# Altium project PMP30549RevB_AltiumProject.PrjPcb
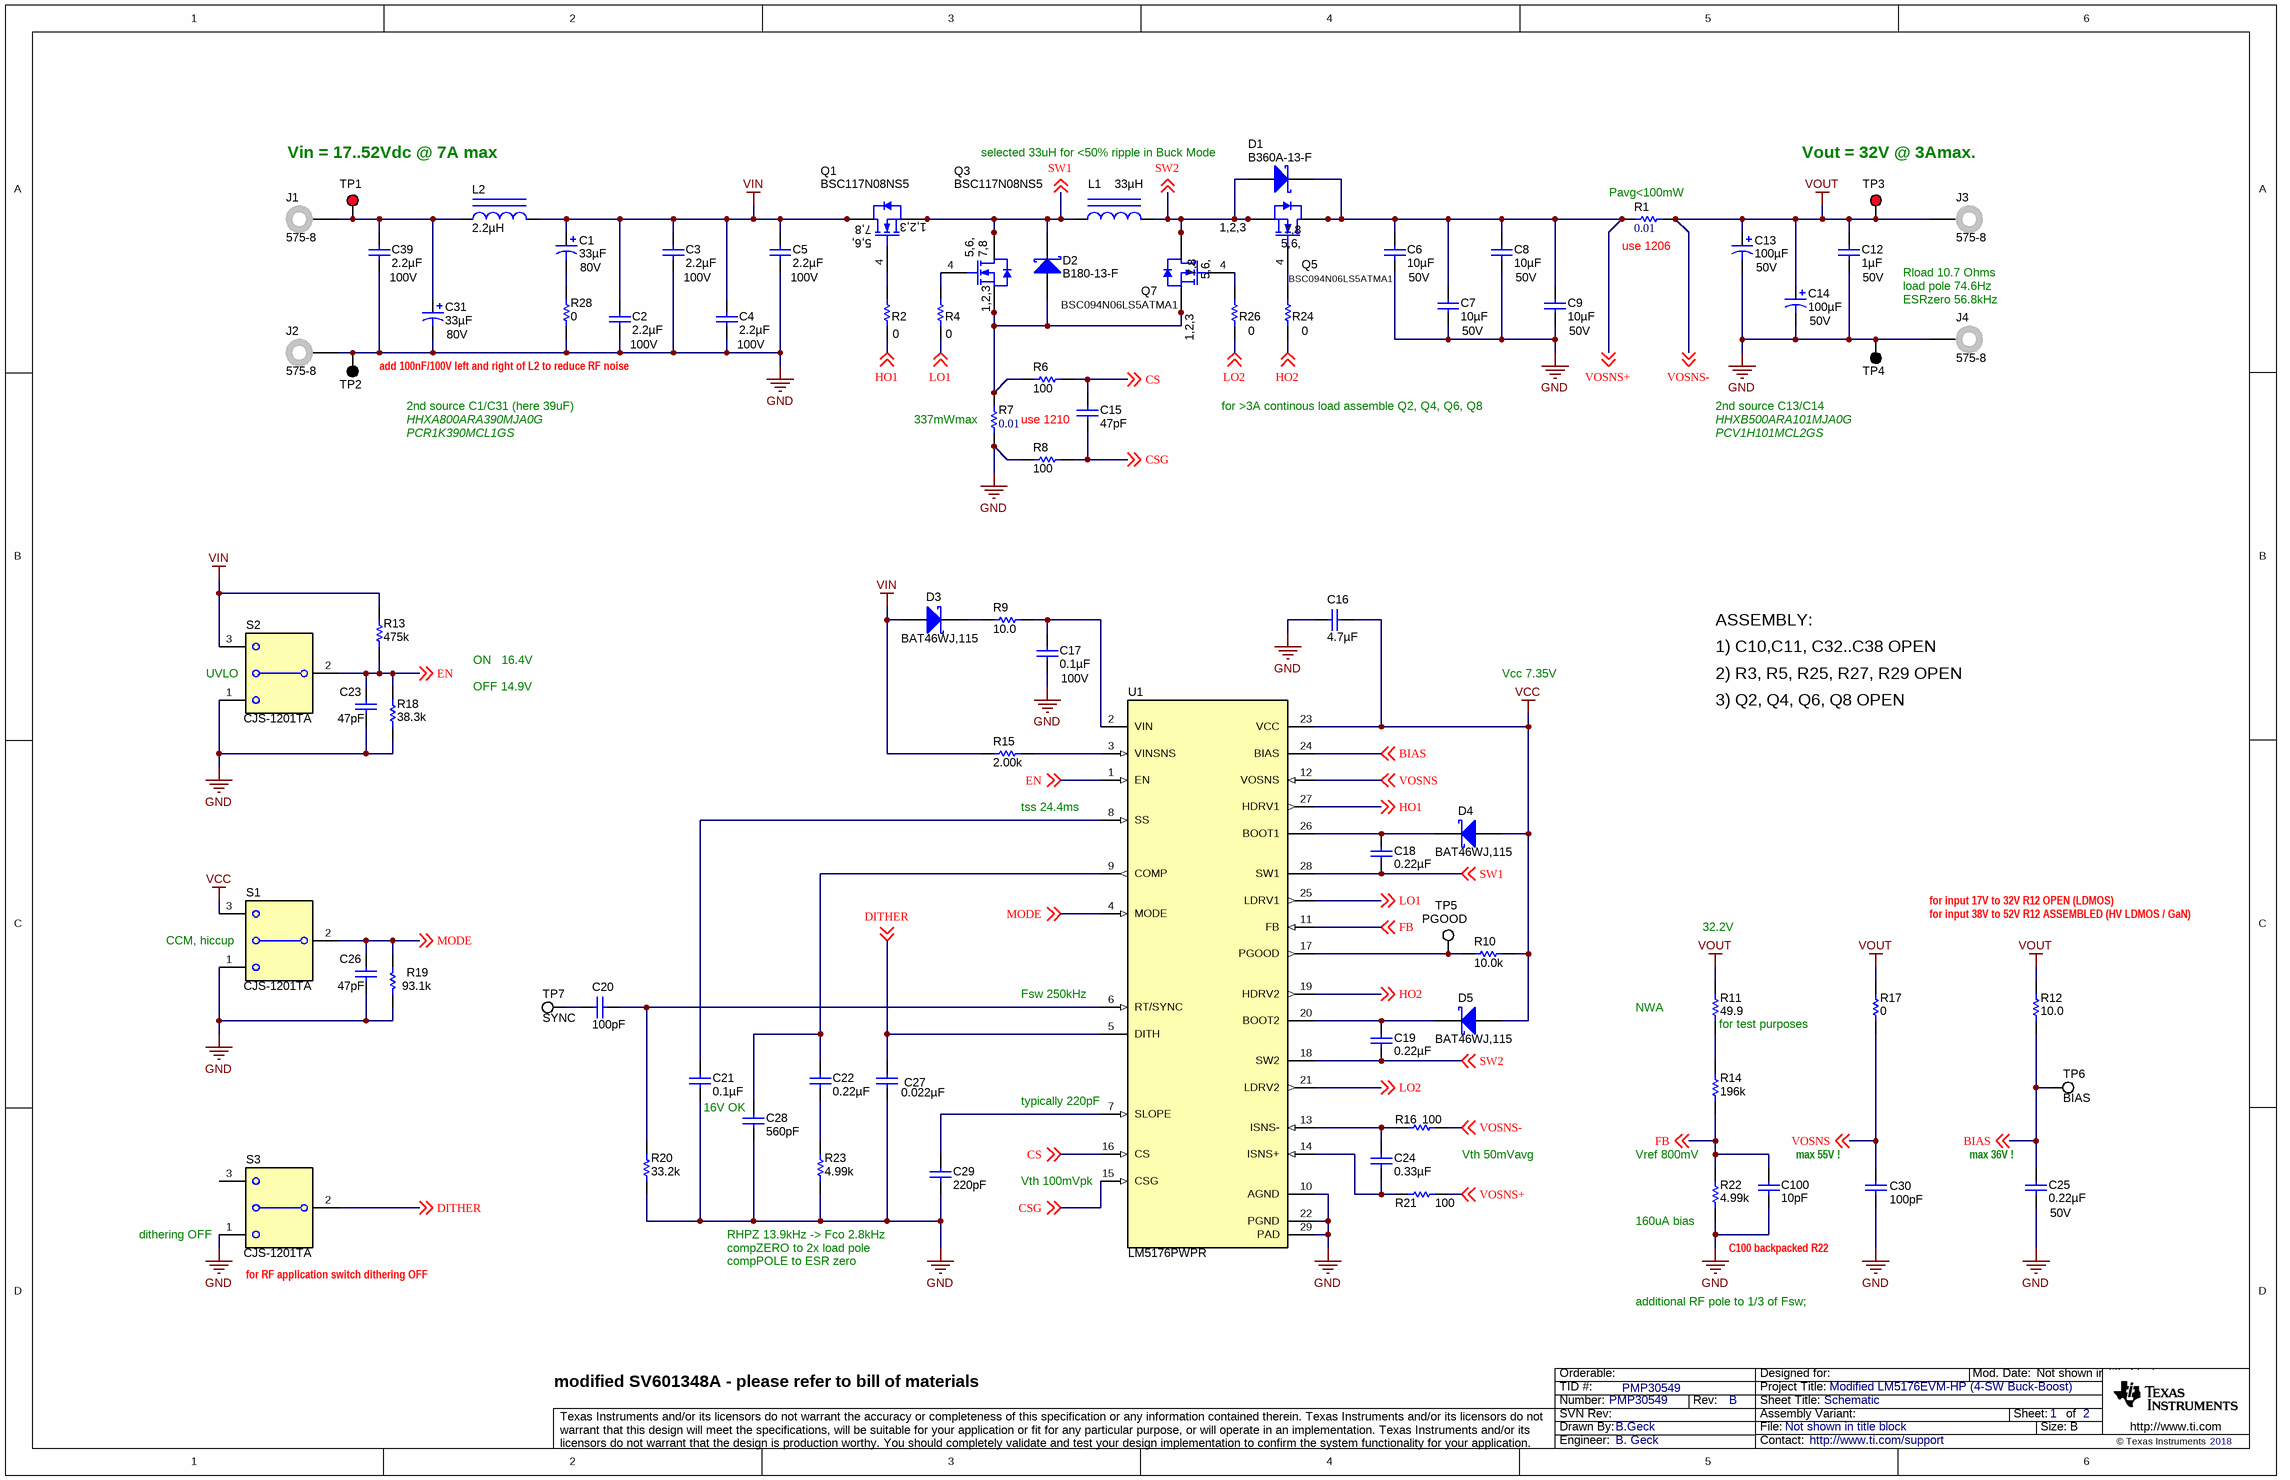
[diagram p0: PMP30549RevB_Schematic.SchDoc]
CopyrightYear: 2018; PCB_Rev: A; PRJ_Engineer: B. Geck; PRJ_Number: PMP30549; PRJ_Title: Modified LM5176EVM-HP (4-SW Buck-Boost); SCH_Rev: B; TechSupport: http://www.ti.com/support; TID: PMP30549
2 sheets, 98 parts. Net scope: global (net labels, ports and power ports of the same name join across sheets).
Sheets:
  PMP30549RevB_Schematic.SchDoc
  PMP30549_EVM_Hardware.SchDoc

## Sheet PMP30549RevB_Schematic.SchDoc: Schematic
size 431 x 279 mm; Date: Not shown in title block; ApprovedBy: Not shown in title block; CheckedBy: Not shown in title block; Author: Not shown in title block; CompanyName: Not shown in title block; DrawnBy: B.Geck; Engineer: Neil Gutierrez; Organization: Not shown in title block; Address1: Not shown in title block; Address2: Not shown in title block; Address3: Not shown in title block; Address4: Not shown in title block; DocumentNumber: 1; Revision: Use project parameter SCH_Rev; SheetNumber: 1; SheetTotal: 2; PageSetup: Record=PageOptions¦CenterHorizontal=True¦CenterVertical=True¦PrintScale=0.62¦XCorrection=1.00¦YCorrection=1.00¦PrintKind=0¦BorderSize=5000000¦LeftOffset=0¦BottomOffset=0¦Orientation=2¦PaperLength=1000¦PaperWidth=1000¦Scale=100¦PaperSource=15¦PrintQuality=600¦MediaType=1¦DitherType=10¦PaperKind=Letter¦PrintScaleMode=1

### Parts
C1  ValueDisplayed: 33µF  Value2: 80V  [SM_RADIAL_10BMM]  (hidden comment: EEHZA1K330P)
C2  ValueDisplayed: 2.2µF  Value2: 100V  [1210_270]  (hidden comment: GRM32ER72A225KA35L)
C3  ValueDisplayed: 2.2µF  Value2: 100V  [1210_270]  (hidden comment: GRM32ER72A225KA35L)
C4  ValueDisplayed: 2.2µF  Value2: 100V  [1210_270]  (hidden comment: GRM32ER72A225KA35L)
C5  ValueDisplayed: 2.2µF  Value2: 100V  [1210_270]  (hidden comment: GRM32ER72A225KA35L)
C6  ValueDisplayed: 10µF  Value2: 50V  [1210_270]  (hidden comment: GRM32ER71H106KA12L)
C7  ValueDisplayed: 10µF  Value2: 50V  [1210_270]  (hidden comment: GRM32ER71H106KA12L)
C8  ValueDisplayed: 10µF  Value2: 50V  [1210_270]  (hidden comment: GRM32ER71H106KA12L)
C9  ValueDisplayed: 10µF  Value2: 50V  [1210_270]  (hidden comment: GRM32ER71H106KA12L)
C12  ValueDisplayed: 1µF  Value2: 50V  [0805_HV]  (hidden comment: GRM21BR71H105KA12L)
C13  ValueDisplayed: 100µF  Value2: 50V  [SM_RADIAL_10BMM]  (hidden comment: EEHZA1H101P)
C14  ValueDisplayed: 100µF  Value2: 50V  [SM_RADIAL_10BMM]  (hidden comment: EEHZA1H101P)
C15  ValueDisplayed: 47pF  [0603L]  (hidden comment: GRM1885C1H470JA01D)
C16  ValueDisplayed: 4.7µF  [0805_HV]  (hidden comment: GRM21BR71C475KA73L)
C17  ValueDisplayed: 0.1µF  Value2: 100V  [0603L]  (hidden comment: GRM188R72A104KA35D)
C18  ValueDisplayed: 0.22µF  [0603L]  (hidden comment: GRM188R71E224KA88D)
C19  ValueDisplayed: 0.22µF  [0603L]  (hidden comment: GRM188R71E224KA88D)
C20  ValueDisplayed: 100pF  [0603L]  (hidden comment: GRM1885C2A101JA01D)
C21  ValueDisplayed: 0.1µF  [0603L]  (hidden comment: GRM188R72A104KA35D)
C22  ValueDisplayed: 0.22µF  [0603]  (hidden comment: GRM188R71E224KA88D)
C23  47pF  [0603L]
C24  ValueDisplayed: 0.33µF  [0603L]  (hidden comment: GRM188R71C334KA01D)
C25  ValueDisplayed: 0.22µF  Value2: 50V  [0603]  (hidden comment: GRM188R71H224KAC4D)
C26  47pF  [0603L]
C27  ValueDisplayed: 0.022µF  [0603L]  (hidden comment: C0603C223K5RACTU)
C28  ValueDisplayed: 560pF  [0603]  (hidden comment: GRM188R71H561KA01D)
C29  ValueDisplayed: 220pF  [0603]  (hidden comment: GRM188R71H221KA01D)
C30  ValueDisplayed: 100pF  [0603L]  (hidden comment: GRM1885C2A101JA01D)
C31  ValueDisplayed: 33µF  Value2: 80V  [SM_RADIAL_10BMM]  (hidden comment: EEHZA1K330P)
C39  ValueDisplayed: 2.2µF  Value2: 100V  [1210_270]  (hidden comment: GRM32ER72A225KA35L)
C100  ValueDisplayed: 10pF  [0603]  (hidden comment: GRM1885C1H100JA01D)
D1  B360A-13-F  [SMA]
D2  B180-13-F  [SMA]
D3  BAT46WJ,115  [SOD-323F]
D4  BAT46WJ,115  [SOD-323F]
D5  BAT46WJ,115  [SOD-323F]
J1  575-8  [Keystone575-8]
J2  575-8  [Keystone575-8]
J3  575-8  [Keystone575-8]
J4  575-8  [Keystone575-8]
L1  ValueDisplayed: 33µH  [XAL1510]  (hidden comment: XAL1510-333MEB)
L2  ValueDisplayed: 2.2µH  [XAL5030]  (hidden comment: XAL5030-222MEB)
Q1  BSC117N08NS5  [PG-TDSON-8]
Q3  BSC117N08NS5  [PG-TDSON-8]
Q5  BSC094N06LS5ATMA1  [PG-TDSON-8]
Q7  BSC094N06LS5ATMA1  [PG-TDSON-8]
R1  ValueDisplayed: 0.01  [2512_WIDE]  (hidden comment: FCSL64R010FER)
R2  value 0  [0603L]  (hidden comment: RC0603JR-070RL)
R4  value 0  [0603L]  (hidden comment: RC0603JR-070RL)
R6  value 100  [0603_HV]  (hidden comment: RC0603FR-07100RL)
R7  ValueDisplayed: 0.01  [2512_WIDE]  (hidden comment: FCSL64R010FER)
R8  value 100  [0603_HV]  (hidden comment: RC0603FR-07100RL)
R9  value 10.0  [0603L]  (hidden comment: RC0603FR-0710RL)
R10  value 10.0k  [0603L]  (hidden comment: RC0603FR-0710KL)
R11  ValueDisplayed: 49.9  [0603]  (hidden comment: CRCW060349R9FKEA)
R12  value 10.0  [0603L]  (hidden comment: RC0603FR-0710RL)
R13  ValueDisplayed: 475k  [0603]  (hidden comment: CRCW0603475KFKEA)
R14  ValueDisplayed: 196k  [0603]  (hidden comment: CRCW0603196KFKEA)
R15  ValueDisplayed: 2.00k  [0603]  (hidden comment: CRCW06032K00FKEA)
R16  100  [0603L]
R17  value 0  [0603L]  (hidden comment: RC0603JR-070RL)
R18  ValueDisplayed: 38.3k  [0603]  (hidden comment: CRCW060338K3FKEA)
R19  ValueDisplayed: 93.1k  [0603L]  (hidden comment: RC0603FR-0793K1L)
R20  ValueDisplayed: 33.2k  [0603L]  (hidden comment: CRCW060333K2FKEA)
R21  100  [0603L]
R22  ValueDisplayed: 4.99k  [0603]  (hidden comment: CRCW06034K99FKEA)
R23  ValueDisplayed: 4.99k  [0603]  (hidden comment: CRCW06034K99FKEA)
R24  value 0  [0603L]  (hidden comment: RC0603JR-070RL)
R26  value 0  [0603L]  (hidden comment: RC0603JR-070RL)
R28  ValueDisplayed: 0  [1206]  (hidden comment: CRCW12060000Z0EA)
S1  CJS-1201TA  [SW_CJS_1201A]
S2  CJS-1201TA  [SW_CJS_1201A]
S3  CJS-1201TA  [SW_CJS_1201A]
TP1  5005  [Keystone5005]  (value not drawn)
TP2  5006  [Keystone5006]  (value not drawn)
TP3  5005  [Keystone5005]  (value not drawn)
TP4  5006  [Keystone5006]  (value not drawn)
TP5  PGOOD  [Keystone5007]
TP6  BIAS  [Keystone5007]
TP7  SYNC  [Keystone5007]
U1  LM5176PWPR  [PWP0028C_N]

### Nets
GND: C2.2 C3.2 C4.2 C5.2 C6.2 C7.2 C8.2 C9.2 C12.2 C13.2(-) C14.2(-) C16.1 C17.2 C21.2 C23.2 C25.2 C26.2 C27.2 C28.2 C29.2 C30.2 C31.2(-) C39.2 C100.2 J2.1 J4.1 R7.1 R8.2 R18.1 R19.1 R20.1 R22.1 R23.1 R28.1 S1.1 S2.1 S3.1 TP2.1 TP4.1 U1.10(AGND) U1.22(PGND) U1.29(PAD)
VCC: C16.2 D4.2(A) D5.2(A) R10.2 S1.3 U1.23(VCC)
VIN: C1.1(+) C2.1 C3.1 C4.1 C5.1 D3.2(A) L2.2 Q1.5(D) Q1.6(D) Q1.7(D) Q1.8(D) Q1.9(D) R13.2 R15.2 S2.3
VOUT: C12.1 C13.1(+) C14.1(+) J3.1 R1.1 R11.2 R12.1 R16.2 R17.1 TP3.1 ; off-sheet VOSNS-  [also labelled VOSNS-]
BIAS: C25.1 R12.2 TP6.1 U1.24(BIAS) ; off-sheet BIAS
CS: C15.1 R6.1 U1.16(CS) ; off-sheet CS
CSG: C15.2 R8.1 U1.15(CSG) ; off-sheet CSG
DITHER: C27.1 S3.2(COM) U1.5(DITH) ; off-sheet DITHER
EN: C23.1 R13.1 R18.2 S2.2(COM) U1.1(EN) ; off-sheet EN
FB: C100.1 R14.1 R22.2 U1.11(FB) ; off-sheet FB
HO1: R2.2 U1.27(HDRV1) ; off-sheet HO1
HO2: R24.2 U1.19(HDRV2) ; off-sheet HO2
LO1: R4.2 U1.25(LDRV1) ; off-sheet LO1
LO2: R26.2 U1.21(LDRV2) ; off-sheet LO2
MODE: C26.1 R19.2 S1.2(COM) U1.4(MODE) ; off-sheet MODE
SW1: C18.1 D2.1(K) L1.1 Q1.1(S) Q1.2(S) Q1.3(S) Q3.5(D) Q3.6(D) Q3.7(D) Q3.8(D) Q3.9(D) U1.28(SW1) ; off-sheet SW1
SW2: C19.2 D1.2(A) L1.2 Q5.1(S) Q5.2(S) Q5.3(S) Q7.5(D) Q7.6(D) Q7.7(D) Q7.8(D) Q7.10(D) U1.18(SW2) ; off-sheet SW2
VOSNS: C30.1 R17.2 U1.12(VOSNS) ; off-sheet VOSNS
VOSNS+: C6.1 C7.1 C8.1 C9.1 D1.1(K) Q5.5(D) Q5.6(D) Q5.7(D) Q5.8(D) Q5.10(D) R1.2 R21.2 ; off-sheet VOSNS+
NetC1_2: C1.2(-) R28.2
NetC17_1: C17.1 R9.1 U1.2(VIN)
NetC18_2: C18.2 D4.1(K) U1.26(BOOT1)
NetC19_1: C19.1 D5.1(K) U1.20(BOOT2)
NetC20_1: C20.1 TP7.1
NetC20_2: C20.2 R20.2 U1.6(RT/SYNC)
NetC21_1: C21.1 U1.8(SS)
NetC22_1: C22.1 C28.1 U1.9(COMP)
NetC22_2: C22.2 R23.2
NetC24_1: C24.1 R16.1 U1.13(ISNS-)
NetC24_2: C24.2 R21.1 U1.14(ISNS+)
NetC29_1: C29.1 U1.7(SLOPE)
NetC31_1: C31.1(+) C39.1 J1.1 L2.1 TP1.1
NetD2_2: D2.2(A) Q3.1(S) Q3.2(S) Q3.3(S) Q7.1(S) Q7.2(S) Q7.3(S) R6.2 R7.2
NetD3_1: D3.1(K) R9.2
NetQ1_4: Q1.4(G) R2.1
NetQ3_4: Q3.4(G) R4.1
NetQ5_4: Q5.4(G) R24.1
NetQ7_4: Q7.4(G) R26.1
NetR10_1: R10.1 TP5.1 U1.17(PGOOD)
NetR11_1: R11.1 R14.2
NetR15_1: R15.1 U1.3(VINSNS)

Not connected (* = marked no-connect by the designer): S3 3

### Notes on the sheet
- Vin = 17..52Vdc @ 7A max
- selected 33uH for <50% ripple in Buck Mode
- Vout = 32V @ 3Amax.
- (near R1) Pavg<100mW
- (near R1) use 1206
- Rload 10.7 Ohms
- load pole 74.6Hz
- ESRzero 56.8kHz
- add 100nF/100V left and right of L2 to reduce RF noise
- HHXA800ARA390MJA0G
- PCR1K390MCL1GS
- 2nd source C1/C31 (here 39uF)
- (near R7) 337mWmax
- use 1210
- for >3A continous load assemble Q2, Q4, Q6, Q8
- 2nd source C13/C14
- HHXB500ARA101MJA0G
- PCV1H101MCL2GS
- ASSEMBLY:
- (near S2) UVLO
- ON   16.4V
- OFF 14.9V
- Vcc 7.35V
- 1) C10,C11, C32..C38 OPEN
- 2) R3, R5, R25, R27, R29 OPEN
- 3) Q2, Q4, Q6, Q8 OPEN
- tss 24.4ms
- for input 17V to 32V R12 OPEN (LDMOS)
- (near S1) CCM, hiccup
- 32.2V
- for input 38V to 52V R12 ASSEMBLED (HV LDMOS / GaN)
- (near U1) Fsw 250kHz
- NWA
- (near R11) for test purposes
- 16V OK
- (near U1) typically 220pF
- Vth 50mVavg
- (near R22) Vref 800mV
- max 55V !
- (near C25) max 36V !
- (near S3) dithering OFF
- RHPZ 13.9kHz -> Fco 2.8kHz
- (near U1) Vth 100mVpk
- (near R22) 160uA bias
- (near S3) for RF application switch dithering OFF
- compZERO to 2x load pole
- compPOLE to ESR zero
- additional RF pole to 1/3 of Fsw;
- C100 backpacked R22
- modified SV601348A - please refer to bill of materials

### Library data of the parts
C1 C31 = EEHZA1J560P: CAP, Polymer Hybrid, 33 µF, 80 V,+/- 20%, 36 ohm, 10x10 SMD; Manufacturer: Panasonic; Polarized: Y; CompType: Capacitor; Value: 33uF; U/M: EA; Cap_F: 0.000033; Tolerance_%: 20; Value1: 36 ohm; VDC_V: 80; ESR_ohm: 36; IRMS_A: 1.7; TaMin_C: -55; TaMax_C: 105; SizeAreaWB_mm2: 159.9; SizeArea_mm2: 113.3; SizeX_mm: 11; SizeY_mm: 10.3; SizeZ_mm: 10.2; AEC Category: Q200
C2-C5 C39 = GRM32ER72A225KA35L: CAP, CERM, 2.2 µF, 100 V,+/- 10%, X7R, 1210; Manufacturer: MuRata; Polarized: N; CompType: Capacitor; Value: 2.2uF; U/M: EA; Cap_F: 0.0000022; Tolerance_%: 10; ESR_ohm: 0.007; Value1: 0.007 ohm; VDC_V: 100; IRMS_A: 4.4; TaMin_C: -55; TaMax_C: 125; Cap_Case: 1210; SizeArea_mm2: 8; SizeAreaWB_mm2: 14.7; SizeX_mm: 3.2; SizeY_mm: 2.5; SizeZ_mm: 2.7; AEC Category: Q200; Green_Lifecycle: Active; Green_REACh: Passed
C6-C9 = GRM32ER71H106KA12L: CAP, CERM, 10 µF, 50 V,+/- 10%, X7R, 1210; Manufacturer: MuRata; Polarized: N; CompType: Capacitor; Value: 10uF; U/M: EA; Cap_F: 0.00001; Tolerance_%: 10; VDC_V: 50; TaMin_C: -55; TaMax_C: 125; Cap_Case: 1210; SizeArea_mm2: 8; SizeAreaWB_mm2: 14.7; SizeX_mm: 3.2; SizeY_mm: 2.5; SizeZ_mm: 2.7; AEC Category: Q200; Green_Lifecycle: Active; Green_REACh: Passed
C12 = GRM21BR71H105KA12L: CAP, CERM, 1 µF, 50 V,+/- 10%, X7R, 0805; Manufacturer: MuRata; Polarized: N; CompType: Capacitor; Value: 1uF; U/M: EA; Cap_F: 0.000001; Tolerance_%: 10; VDC_V: 50; TaMin_C: -55; TaMax_C: 125; Cap_Case: 0805; SizeArea_mm2: 2.5; SizeAreaWB_mm2: 6.75; SizeX_mm: 2; SizeY_mm: 1.25; SizeZ_mm: 1.45; AEC Category: Q200; Green_Lifecycle: Active; Green_REACh: Passed
C13 C14 = EEHZA1H101P: CAP, Polymer Hybrid, 100 µF, 50 V,+/- 20%, 28 ohm, 10x10 SMD; Manufacturer: Panasonic; Polarized: Y; CompType: Capacitor; Value: 100uF; U/M: EA; Cap_F: 0.0001; Tolerance_%: 20; Value1: 28 ohm; VDC_V: 50; ESR_ohm: 28; IRMS_A: 2; TaMin_C: -55; TaMax_C: 105; SizeAreaWB_mm2: 159.9; SizeArea_mm2: 113.3; SizeX_mm: 11; SizeY_mm: 10.3; SizeZ_mm: 10.2; AEC Category: Q200
C15 C23 C26 = GRM1885C1H470JA01D: CAP, CERM, 47pF, 50V, +/-5%, C0G/NP0, 0603; Manufacturer: MuRata; Polarized: N; CompType: Capacitor; U/M: EA; Cap_F: 0.000000000047; Tolerance_%: 5; Value1: Unknown; VDC_V: 50; TaMin_C: -55; TaMax_C: 125; Cap_Case: 0603
C16 = GRM21BR71C475KA73L: CAP, CERM, 4.7 µF, 16 V, +/- 10%, X7R, 0805; Manufacturer: MuRata; Polarized: N; CompType: Capacitor; Value: 4.7uF; U/M: EA; Cap_F: 0.0000047; Tolerance_%: 10; ESR_ohm: 0.006; Value1: 0.006 ohm; VDC_V: 16; Value2: 16V; TaMin_C: -55; TaMax_C: 125; Cap_Case: 0805
C17 C21 = GRM188R72A104KA35D: CAP, CERM, 0.1uF, 100V, +/-10%, X7R, 0603; Manufacturer: MuRata; Polarized: N; CompType: Capacitor; U/M: EA; Cap_F: 0.0000001; Tolerance_%: 10; Value1: Unknown; VDC_V: 100; TaMin_C: -55; TaMax_C: 125; Cap_Case: 0603
C18 C19 = GRM188R71E224KA88D: CAP, CERM, 0.22 µF, 25 V, +/- 10%, X7R, 0603; Manufacturer: MuRata; Polarized: N; CompType: Capacitor; Value: 0.22uF; U/M: EA; Cap_F: 0.00000022; Tolerance_%: 10; Value1: Unknown; VDC_V: 25; Value2: 25V; TaMin_C: -55; TaMax_C: 125; Cap_Case: 0603
C20 C30 = GRM1885C2A101JA01D: CAP, CERM, 100pF, 100V, +/-5%, C0G/NP0, 0603; Manufacturer: MuRata; Polarized: N; CompType: Capacitor; U/M: EA; Cap_F: 0.0000000001; Tolerance_%: 5; Value1: Unknown; VDC_V: 100; TaMin_C: -55; TaMax_C: 125; Cap_Case: 0603
C22 = GRM188R71E224KA88D: CAP, CERM, 0.22 µF, 25 V,+/- 10%, X7R, 0603; Manufacturer: MuRata; Polarized: N; CompType: Capacitor; Value: 0.22uF; U/M: EA; Cap_F: 0.00000022; Tolerance_%: 10; VDC_V: 25; Value2: 25V; TaMin_C: -55; TaMax_C: 125; SizeArea_mm2: 1.28; SizeAreaWB_mm2: 4.68; SizeX_mm: 1.6; SizeY_mm: 0.8; SizeZ_mm: 1; AEC Category: Q200; Green_Lifecycle: Active; Green_REACh: Passed
C24 = GRM188R71C334KA01D: CAP, CERM, 0.33 µF, 16 V, +/- 10%, X7R, 0603; Manufacturer: MuRata; Polarized: N; CompType: Capacitor; Value: 0.33uF; U/M: EA; Cap_F: 0.00000033; Tolerance_%: 10; Value1: Unknown; VDC_V: 16; Value2: 16V; TaMin_C: -55; TaMax_C: 125; Cap_Case: 0603
C25 = GRM188R71H224KAC4D: CAP, CERM, 0.22 µF, 50 V,+/- 10%, X7R, 0603; Manufacturer: MuRata; Polarized: N; CompType: Capacitor; Value: 0.22uF; U/M: EA; Cap_F: 0.00000022; Tolerance_%: 10; VDC_V: 50; TaMin_C: -55; TaMax_C: 125; SizeArea_mm2: 1.28; SizeAreaWB_mm2: 4.68; SizeX_mm: 1.6; SizeY_mm: 0.8; SizeZ_mm: 1; AEC Category: Q200
C27 = C0603C223K5RACTU: CAP, CERM, 0.022uF, 50V, +/-10%, X7R, 0603; Manufacturer: Kemet; Polarized: N; CompType: Capacitor; U/M: EA; Cap_F: 0.000000022; Tolerance_%: 10; Value1: Unknown; VDC_V: 50; TaMin_C: -55; TaMax_C: 125; Cap_Case: 0603
C28 = GRM188R71H561KA01D: CAP, CERM, 560 pF, 50 V,+/- 10%, X7R, 0603; Manufacturer: MuRata; Polarized: N; CompType: Capacitor; Value: 560pF; U/M: EA; Cap_F: 0.00000000056; Tolerance_%: 10; VDC_V: 50; Value2: 50V; TaMin_C: -55; TaMax_C: 125; SizeArea_mm2: 1.28; SizeAreaWB_mm2: 4.68; SizeX_mm: 1.6; SizeY_mm: 0.8; SizeZ_mm: 1; AEC Category: Q200
C29 = GRM188R71H221KA01D: CAP, CERM, 220 pF, 50 V,+/- 10%, X7R, 0603; Manufacturer: MuRata; Polarized: N; CompType: Capacitor; Value: 220pF; U/M: EA; Cap_F: 0.00000000022; Tolerance_%: 10; VDC_V: 50; Value2: 50V; TaMin_C: -55; TaMax_C: 125; SizeArea_mm2: 1.28; SizeAreaWB_mm2: 4.68; SizeX_mm: 1.6; SizeY_mm: 0.8; SizeZ_mm: 1; AEC Category: Q200; Green_Lifecycle: Active; Green_REACh: Passed
C100 = GRM1885C1H100JA01D: CAP, CERM, 10 pF, 50 V,+/- 5%, C0G/NP0, 0603; Manufacturer: MuRata; Polarized: N; CompType: Capacitor; Value: 10pF; U/M: EA; Cap_F: 0.00000000001; Tolerance_%: 5; VDC_V: 50; Value2: 50V; TaMin_C: -55; TaMax_C: 125; SizeArea_mm2: 1.28; SizeAreaWB_mm2: 4.68; SizeX_mm: 1.6; SizeY_mm: 0.8; SizeZ_mm: 1; AEC Category: Q200; Green_Lifecycle: Active; Green_REACh: Passed
D1 = B360A-13-F: Diode, Schottky, 60 V, 3 A, SMA; Manufacturer: Diodes Inc.; U/M: EA; Vf_V: 0.7; Value: 60V; Value1: 3A; Value2: 0.7V; Io_A: 3; Vr_V: 60; TJmax_C: 125; RJC_CperW: 25; SizeAreaWB_mm2: 37.3428; SizeArea_mm2: 16.3228; SizeX_mm: 5.59; SizeY_mm: 2.92; SizeZ_mm: 2.87; AEC Category: Q101; Green_Lifecycle: Active; Green_REACh: Passed
D2 = B180-13-F: Diode, Schottky, 80 V, 1 A, SMA; Manufacturer: Diodes Inc.; U/M: EA; Vf_V: 0.79; Value: 80V; Value1: 1A; Value2: 0.79V; Io_A: 1; Vr_V: 80; TJmax_C: 150; RJC_CperW: 25; SizeAreaWB_mm2: 37.3428; SizeArea_mm2: 16.3228; SizeX_mm: 5.59; SizeY_mm: 2.92; SizeZ_mm: 2.87; AEC Category: Q101; Green_Lifecycle: Not Set; Green_REACh: Incomplete
D3-D5 = BAT46WJ,115: Diode, Schottky, 100 V, 0.25 A, SOD-323F; Manufacturer: Nexperia; U/M: EA; Vf_V: 0.85; Value: 100V; Value1: 0.25A; Value2: 0.85V; Io_A: 0.25; Vr_V: 100; TJmax_C: 150; SizeAreaWB_mm2: 7.875; SizeArea_mm2: 3.125; SizeX_mm: 2.5; SizeY_mm: 1.25; SizeZ_mm: 0.8; AEC Category: Q101; Green_Lifecycle: Not Set; Green_REACh: Incomplete
J1-J4 = 575-8: Standard Banana Jack, Uninsulated, 8.9mm; Manufacturer: Keystone; CompType: Connector
L1 = XAL1510-223MEB: Inductor, Shielded, Composite, 33 µH, 8.6 Arms, 0.02 ohm, SMD; Manufacturer: Coilcraft; Value: 33uH; Ind_H: 33.0E-6; Imax_A: 8.6; Irms: 12A @ 40C rise; Isat: 16.7A @ 30% inductance drop; DCR_ohm: 0.02; Value2: 8.6A; SizeAreaWB_mm2: 320.16; SizeArea_mm2: 252.56; SizeX_mm: 16.4; SizeY_mm: 15.4; SizeZ_mm: 10; AEC Category: Q200
L2 = XAL5030-222MEB: Inductor, Shielded, Composite, 2.2 µH, 9.2 A, 0.01 ohm, SMD; Manufacturer: Coilcraft; Value: 2.2uH; Ind_H: 2.2E-6; Imax_A: 9.2; Irms: 9.2A @ 40C rise; Isat: 12.9A @ 30% inductance drop; DCR_ohm: 0.01; Value2: 9.2A; SizeAreaWB_mm2: 54.4544; SizeArea_mm2: 28.9344; SizeX_mm: 5.28; SizeY_mm: 5.48; SizeZ_mm: 3.1; AEC Category: Q200; Green_Lifecycle: Not Set; Green_REACh: Incomplete
Q1 Q3 = BSC117N08NS5ATMA1: MOSFET, N-CH, 80 V, 49 A, PG-TDSON-8; Manufacturer: Infineon Technologies; Alternate Manufacturer: None; U/M: EA; ChType: N; Value: 80V; VdsMax_V: 80; Value1: ? ohm; Value2: 15 nC; QgTyp_nC: 15; Vgs_V: 20; IdsMax_A: 49; SizeAreaWB_mm2: 55.131; SizeArea_mm2: 29.351; SizeX_mm: 5.99; SizeY_mm: 4.9; SizeZ_mm: 1.12; AEC Category: Q101; Green_Lifecycle: Not Set; Green_REACh: Incomplete
Q5 Q7 = MOSFET_N_D5678_10G4S123: MOSFET, N-CH, 60V, 47A, PG-TDSON-8; Manufacturer: Infineon; U/M: EA
R1 R7 = FCSL64R010FER: RES, 0.01, 1%, 2 W, 2512 WIDE; Manufacturer: Ohmite; CompType: Resistor; Value: 0.01; Value_Code: R010; Tolerance_%: 1; Power_W: 2; Value2: 2W; TempCo: 75 ppm/C; SizeArea_mm2: 20.16; SizeAreaWB_mm2: 43.16; SizeX_mm: 3.2; SizeY_mm: 6.3; SizeZ_mm: 0.7; EIA_Code: E96; U/M: EA; AEC Category: Q200
R2 R4 R17 R24 R26 = RC0603JR-070RL: RES, 0 ohm, 5%, 0.1W, 0603; Manufacturer: Yageo America; CompType: Resistor; Value_Code: 0000; Tolerance_%: 5; Power_W: 0.1; VDC_V: 50; TempCo: 200 ppm/C; EIA_Code: E24; U/M: EA
R6 R8 R16 R21 = RC0603FR-07100RL: RES, 100 ohm, 1%, 0.1W, 0603; Manufacturer: Yageo America; CompType: Resistor; Value_Code: 100R; Tolerance_%: 1; Power_W: 0.1; VDC_V: 150; TempCo: 200 ppm/C; EIA_Code: E96; U/M: EA
R9 R12 = RC0603FR-0710RL: RES, 10.0 ohm, 1%, 0.1W, 0603; Manufacturer: Yageo America; CompType: Resistor; Res_ohm: 10; Value_Code: 10R0; Tolerance_%: 1; Power_W: 0.1; VDC_V: 150; TempCo: 200 ppm/C; EIA_Code: E96; U/M: EA
R10 = RC0603FR-0710KL: RES, 10.0k ohm, 1%, 0.1W, 0603; Manufacturer: Yageo America; CompType: Resistor; Res_ohm: 10000; Value_Code: 10k0; Tolerance_%: 1; Power_W: 0.1; VDC_V: 150; TempCo: 200 ppm/C; EIA_Code: E96; U/M: EA
R11 = CRCW060349R9FKEA: RES, 49.9, 1%, 0.1 W, 0603; Manufacturer: Vishay-Dale; CompType: Resistor; Value: 49.9; Value_Code: 49R9; Tolerance_%: 1; Power_W: 0.1; Value2: 0.1W; VDC_V: 75; TempCo: 100 ppm/C; SizeArea_mm2: 1.28; SizeX_mm: 1.6; SizeY_mm: 0.8; EIA_Code: E96; U/M: EA; AEC Category: Q200; Green_Lifecycle: Active; Green_REACh: Passed
R13 = CRCW0603475KFKEA: RES, 475 k, 1%, 0.1 W, 0603; Manufacturer: Vishay-Dale; CompType: Resistor; Value: 475k; Res_ohm: 475000; Tolerance_%: 1; Power_W: 0.1; Value2: 0.1W; VDC_V: 75; TempCo: 100 ppm/C; SizeArea_mm2: 1.28; SizeX_mm: 1.6; SizeY_mm: 0.8; EIA_Code: E96; U/M: EA; AEC Category: Q200; Green_Lifecycle: Active; Green_REACh: Passed
R14 = CRCW0603196KFKEA: RES, 196 k, 1%, 0.1 W, 0603; Manufacturer: Vishay-Dale; CompType: Resistor; Value: 196k; Res_ohm: 196000; Tolerance_%: 1; Power_W: 0.1; Value2: 0.1W; VDC_V: 75; TempCo: 100 ppm/C; SizeArea_mm2: 1.28; SizeX_mm: 1.6; SizeY_mm: 0.8; EIA_Code: E96; U/M: EA; AEC Category: Q200; Green_Lifecycle: Active; Green_REACh: Passed
R15 = CRCW06032K00FKEA: RES, 2.00 k, 1%, 0.1 W, 0603; Manufacturer: Vishay-Dale; CompType: Resistor; Value: 2.00k; Res_ohm: 2000; Value_Code: 2k00; Tolerance_%: 1; Power_W: 0.1; Value2: 0.1W; VDC_V: 75; TempCo: 100 ppm/C; EIA_Code: E96; U/M: EA; SizeArea_mm2: 1.28; SizeX_mm: 1.6; SizeY_mm: 0.8; AEC Category: Q200
R18 = CRCW060338K3FKEA: RES, 38.3 k, 1%, 0.1 W, 0603; Manufacturer: Vishay-Dale; CompType: Resistor; Value: 38.3k; Res_ohm: 38300; Value_Code: 38k3; Tolerance_%: 1; Power_W: 0.1; Value2: 0.1W; VDC_V: 75; TempCo: 100 ppm/C; SizeArea_mm2: 1.28; SizeX_mm: 1.6; SizeY_mm: 0.8; EIA_Code: E96; U/M: EA; AEC Category: Q200; Green_Lifecycle: Active; Green_REACh: Passed
R19 = RC0603FR-0793K1L: RES, 93.1 k, 1%, 0.1 W, 0603; Manufacturer: Yageo America; CompType: Resistor; Value: 93.1k; Res_ohm: 93100; Value_Code: 93k1; Tolerance_%: 1; Power_W: 0.1; Value2: 0.1W; VDC_V: 150; TempCo: 200 ppm/C; EIA_Code: E96; U/M: EA
R20 = CRCW060333K2FKEA: RES, 33.2 k, 1%, 0.1 W, 0603; Manufacturer: Vishay-Dale; CompType: Resistor; Value: 33.2k; Res_ohm: 33200; Value_Code: 33k2; Tolerance_%: 1; Power_W: 0.1; Value2: 0.1W; VDC_V: 75; TempCo: 100 ppm/C; EIA_Code: E96; U/M: EA; SizeArea_mm2: 1.28; SizeX_mm: 1.6; SizeY_mm: 0.8; AEC Category: Q200
R22 R23 = CRCW06034K99FKEA: RES, 4.99 k, 1%, 0.1 W, 0603; Manufacturer: Vishay-Dale; CompType: Resistor; Value: 4.99k; Res_ohm: 4990; Value_Code: 4k99; Tolerance_%: 1; Power_W: 0.1; Value2: 0.1W; VDC_V: 75; TempCo: 100 ppm/C; SizeArea_mm2: 1.28; SizeX_mm: 1.6; SizeY_mm: 0.8; EIA_Code: E96; U/M: EA; AEC Category: Q200; Green_Lifecycle: Active; Green_REACh: Passed
R28 = CRCW12060000Z0EA: RES, 0, 5%, 0.25 W, 1206; Manufacturer: Vishay-Dale; CompType: Resistor; Value: 0; Value_Code: 0000; Tolerance_%: 5; Power_W: 0.25; Value2: 0.25W; VDC_V: 200; TempCo: 200 ppm/C; SizeArea_mm2: 5.12; SizeX_mm: 3.2; SizeY_mm: 1.6; SizeZ_mm: 1.35; EIA_Code: E24; U/M: EA; AEC Category: Q200
S1-S3 = CJS-1201TA: Slide SW, SPDT 0.1A 50VDC; Manufacturer: Copal Electronics; SymbolCreator: a0799628; VDC_V: 50; SwitchFunction: On-Off-On; PositionCount: 1; CurrentRating_mA: 100; CompType: Switch
TP1 TP3 = 5005: Test Point, Compact, Red, TH; Manufacturer: Keystone; CompType: Test Point Loop; U/M: EA
TP2 TP4 = 5006: Test Point, Compact, Black, TH; Manufacturer: Keystone; CompType: Test Point Loop; U/M: EA
TP5-TP7 = 5007: Test Point, Compact, White, TH; Manufacturer: Keystone; CompType: Test Point Loop; U/M: EA
U1 = LM5176PWPR: 55 V Wide VIN Synchronous 4-Switch Buck-Boost Controller, PWP0028C (TSSOP-28); Alternate PartNumber: LM5176PWPT; Manufacturer: Texas Instruments; SymbolCreator: a0411947; SizeArea_mm2: 62.08; SizeAreaWB_mm2: 98.28; SizeX_mm: 6.4; SizeY_mm: 9.7; SizeZ_mm: 1.2; CompType: IC; U/M: EA

## Sheet PMP30549_EVM_Hardware.SchDoc: Hardware
size 431 x 279 mm; Date: Not shown in title block; ApprovedBy: Not shown in title block; CheckedBy: Not shown in title block; Author: Not shown in title block; CompanyName: Not shown in title block; Engineer: Not shown in title block; Organization: Not shown in title block; Address1: Not shown in title block; Address2: Not shown in title block; Address3: Not shown in title block; Address4: Not shown in title block; DocumentNumber: 2; Revision: Use project parameter SCH_Rev; SheetNumber: 2; SheetTotal: 2; PageSetup: Record=PageOptions¦CenterHorizontal=True¦CenterVertical=True¦PrintScale=1.00¦XCorrection=1.00¦YCorrection=1.00¦PrintKind=0¦BorderSize=5000000¦LeftOffset=0¦BottomOffset=0¦Orientation=2¦PaperLength=1000¦PaperWidth=1000¦Scale=100¦PaperSource=15¦PrintQuality=600¦MediaType=1¦DitherType=10¦PaperKind=Letter¦PrintScaleMode=1
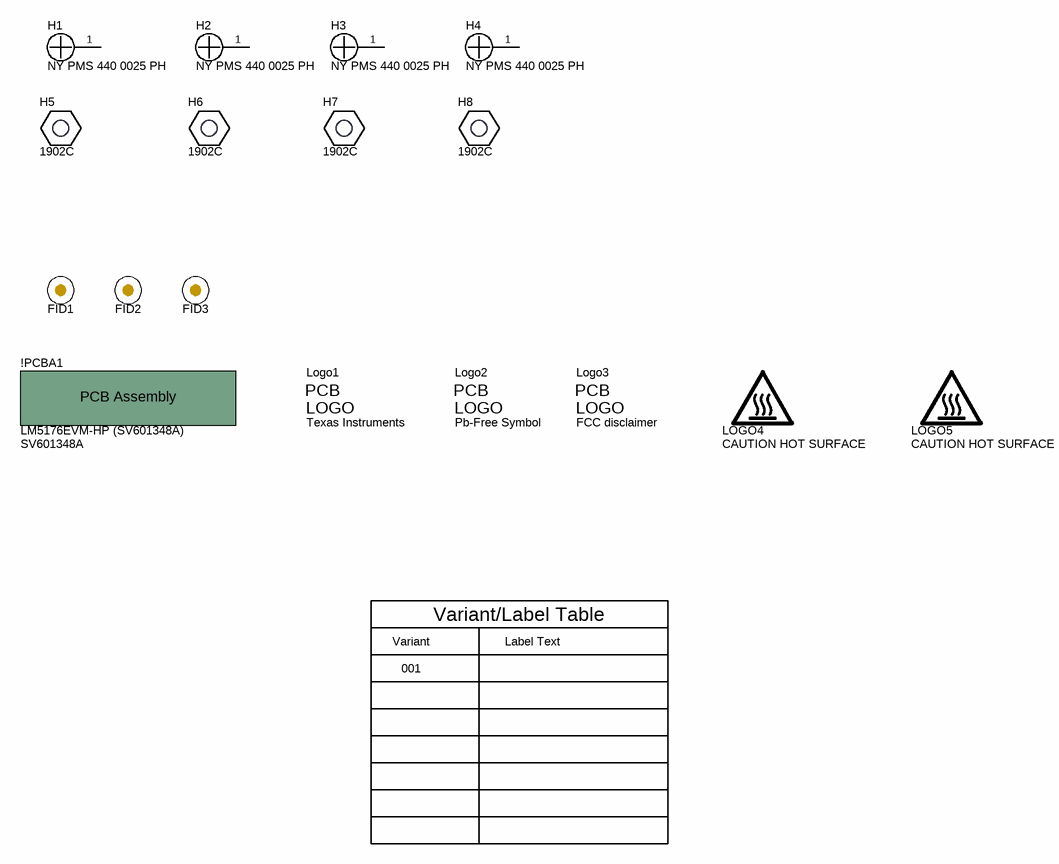
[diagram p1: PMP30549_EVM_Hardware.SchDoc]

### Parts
!PCBA1  LM5176EVM-HP (SV601348A)  PartNumber: SV601348A  (mechanical)
FID1  Fiducial  [Fiducial10-20]  (value not drawn)
FID2  Fiducial  [Fiducial10-20]  (value not drawn)
FID3  Fiducial  [Fiducial10-20]  (value not drawn)
H1  NY PMS 440 0025 PH  [NY PMS 440 0025 PH]
H2  NY PMS 440 0025 PH  [NY PMS 440 0025 PH]
H3  NY PMS 440 0025 PH  [NY PMS 440 0025 PH]
H4  NY PMS 440 0025 PH  [NY PMS 440 0025 PH]
H5  1902C  [Keystone_1902C]
H6  1902C  [Keystone_1902C]
H7  1902C  [Keystone_1902C]
H8  1902C  [Keystone_1902C]
Logo1  Texas Instruments  [TI_Stacked_Overlay_Small]  (no BOM)
Logo2  Pb-Free Symbol  [Pb-Free_Overlay_Small]  (no BOM)
Logo3  FCC disclaimer  [FCC_disclaimer]  (no BOM)
LOGO4  CAUTION HOT SURFACE  [IEC_HotSurface_Large]  (no BOM)
LOGO5  CAUTION HOT SURFACE  [IEC_HotSurface_Large]  (no BOM)

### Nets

Not connected (* = marked no-connect by the designer): H1 1; H2 1; H3 1; H4 1

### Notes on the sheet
- Variant
- Variant/Label Table
- Label Text
- 001

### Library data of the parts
!PCBA1 = PCBA: Manufacturer: Any; SymbolCreator: a0412235; U/M: EA
FID1-FID3 = Fiducial: Fiducial mark.  There is nothing to buy or mount.; SymbolCreator: codlsc
H1-H4 = NY PMS 440 0025 PH: Machine Screw, Round, #4-40 x 1/4, Nylon, Philips panhead; Manufacturer: B&F Fastener Supply; CompType: Hardware; SymbolCreator: codlsc; U/M: EA; Green_Lifecycle: Not Set; Green_REACh: Incomplete
H5-H8 = 1902C: Standoff, Hex, 0.5"L #4-40 Nylon; Manufacturer: Keystone; Green_Lifecycle: Active; Green_REACh: Passed; SymbolCreator: a0412235
Logo1 = TI_Logo: Texas Instrument Corporate Signature; SymbolCreator: a0412235
Logo2 = Pb-Free: SymbolCreator: a0412235
Logo3 = FCC_disclaimer: SymbolCreator: a0412235
LOGO4 LOGO5 = IEC_HotSurface: IEC 61010-1 Hot Surface Warning; SymbolCreator: a0412235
